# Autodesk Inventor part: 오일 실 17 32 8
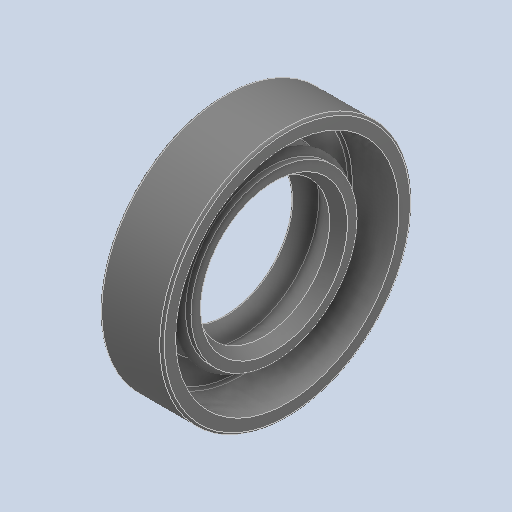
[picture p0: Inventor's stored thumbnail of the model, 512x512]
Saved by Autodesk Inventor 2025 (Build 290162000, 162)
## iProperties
Created: 2024-08
Part Number: 오일 실 17 32 8
Material: 고무
Description: 오일-실
Document SubType Name: Modeling
Designer: rese9
Density: 0.93 g/cm^3
Appearance: 기본값
Author: jhkim
Sending System: Autodesk Inventor 2025
Preprocessor: ST-DEVELOPER v20
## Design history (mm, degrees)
feature "Solid1"
node "솔리드1"
